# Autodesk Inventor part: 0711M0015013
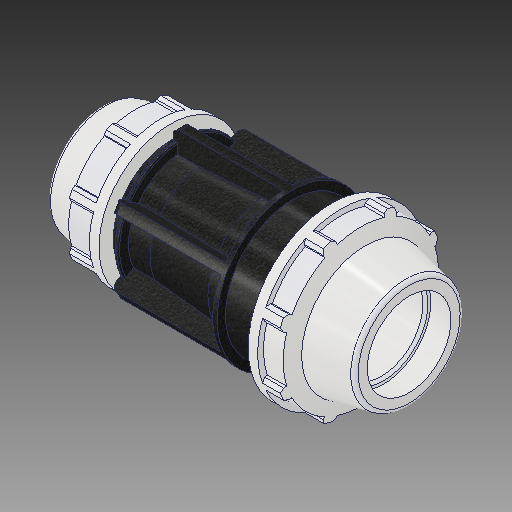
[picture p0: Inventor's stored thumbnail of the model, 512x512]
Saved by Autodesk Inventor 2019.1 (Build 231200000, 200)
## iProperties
Created: 2017-02
Part Number: 0711M0015013
Material: PVC-Piping
Description: PLASSON REDUCING COUPLER 1 1/2'' - 1 1/4''
Document SubType Name: Modeling
Designer: KIM
Mass: 92.6774 g
Surface Area: 199.44 cm^2
Volume: 66.1981 cm^3
Density: 1.4 g/cm^3
Appearance: PTFE
Author: KIM
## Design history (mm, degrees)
derived "0711M0.ipt"
feature "Solid1::0711M0.ipt"
tag "TaggingFeature1"
body "Solid1"
other parameters: "d_" = 48.1, "E_" = 96.012, "H_" = 176, "l_" = 82.042, "d_1" = 42.1, "E_1" = 82.042, "l_1" = 58, "d96" = 9.8542, "d2" = 48.1, "d4" = 14.66667, "d5" = 25.14286, "d7" = 96.012, "d9" = 25.14286, "d11" = 2.51429, "d12" = 76.8096, "d13" = 120 deg, "d14" = 62.53, "d15" = 12 deg, "d16" = 86.4108, "d18" = 2.405, "d19" = 35 deg, "d20" = 17.5 deg, "d21" = 89.29116, "d23" = 0, "d25" = 360 deg, "d27" = 1.92024, "d42" = 19.36, "d46" = 1.443, "d51" = 176, "d52" = 60.68966, "d53" = 12 deg, "d54" = 82.042, "d56" = 63.15, "d57" = 42.1, "d58" = 43.29, "d59" = 37.89, "d60" = 73.8378, "d61" = 65.6336, "d62" = 17.6, "d63" = 21.12, "d64" = 120 deg, "d65" = 82.042, "d68" = 12.57143, "d74" = 76.29906, "d75" = 35 deg, "d76" = 17.5 deg, "d78" = 0, "d80" = 360 deg, "d85" = 1.64084, "d88" = 0.842, "d93" = 58, "d94" = 67.2084, "d97" = 3.28473, "d98" = 5.46947, "d99" = 0, "d100" = 3.84048, "d102" = 360 deg, "d104" = 2, "d106" = 0, "d107" = 5.46947, "d108" = 0, "d109" = 5.46947, "d110" = 0
